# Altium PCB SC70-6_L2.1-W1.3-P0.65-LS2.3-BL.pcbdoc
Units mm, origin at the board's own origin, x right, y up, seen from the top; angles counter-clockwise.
Board outline 15.2 x 15.8 mm, 2 copper layers (Top Layer, Bottom Layer), stack 0 mm thick; 1 components, 0 nets, 6 pads, 0 vias.
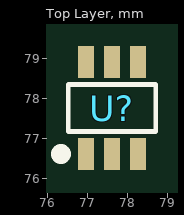
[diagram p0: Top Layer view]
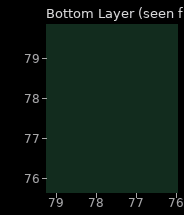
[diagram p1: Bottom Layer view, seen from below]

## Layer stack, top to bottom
Top Layer: signal copper (thickness not stored)
Bottom Layer: signal copper (thickness not stored)

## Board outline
85.046,69.85 69.85,69.85 69.85,85.65 85.046,85.65

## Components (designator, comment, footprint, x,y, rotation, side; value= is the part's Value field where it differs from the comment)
U? "" SC70-6_L2.1-W1.3-P0.65-LS2.3-BL 77.596,77.75 r0 top

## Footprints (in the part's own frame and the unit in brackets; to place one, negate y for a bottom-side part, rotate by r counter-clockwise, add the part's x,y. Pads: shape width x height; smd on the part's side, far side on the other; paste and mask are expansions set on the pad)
SC70-6_L2.1-W1.3-P0.65-LS2.3-BL [mm]
  rect 0.4x0.8 smd: 1(-0.65,-1.15) 2(0,-1.15) 3(0.65,-1.15) 4(0.65,1.15) 5(0,1.15) 6(-0.65,1.15)
  silkscreen extent -1.4,-1.27 1.1,0.59

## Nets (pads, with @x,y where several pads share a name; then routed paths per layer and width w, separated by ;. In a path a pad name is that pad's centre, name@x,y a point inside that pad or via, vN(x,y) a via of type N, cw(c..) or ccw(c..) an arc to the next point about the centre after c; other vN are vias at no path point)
pads on no net: U?.1 U?.2 U?.3 U?.4 U?.5 U?.6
